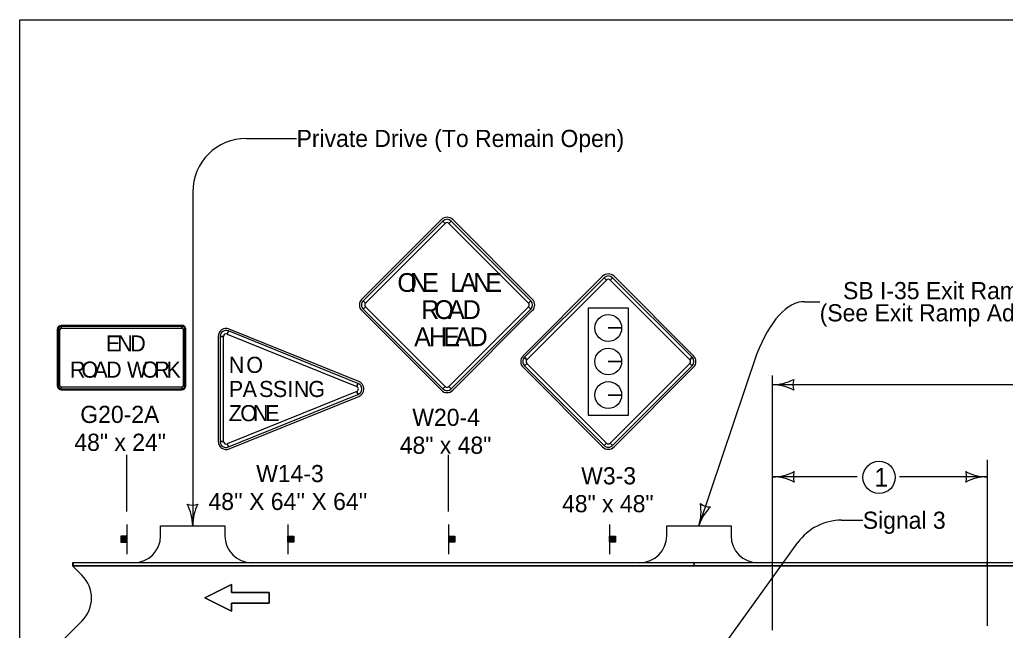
# Model space of a CAD drawing. Extents: x -2134934 to -2122394, y -2139046 to -2137036.
# Drawn here: x -2130232 to -2129313, y -2137605 to -2137036 of the extents above; entities that cross this region are included whole.
import ezdxf

# ---------------------------------------------------------------- set-up
doc = ezdxf.new("R2010")
doc.units = 0
for name, color, linetype in [('Barrier', 7, 'Continuous'), ('BridgeSuperStructureExisting', 7, 'Continuous'), ('Default', 7, 'Continuous'), ('DsnShtPlotIdentification', 7, 'Continuous'), ('DsnShtPlotShape', 7, 'Continuous')]:
    doc.layers.add(name, color=color, linetype=linetype)

msp = doc.modelspace()

# ---------------------------------------------------------------- linework, layer by layer
at = {"layer": 'Barrier'}
for p, q in [((-2129838.72, -2137222.31), (-2129912.96, -2137296.56)), ((-2129837.39, -2137223.64), (-2129835.18, -2137225.85)), ((-2129831.65, -2137225.85), (-2129829.44, -2137223.64)), ((-2129753.86, -2137296.56), (-2129828.11, -2137222.31)), ((-2129688.28, -2137275.12), (-2129762.53, -2137349.37)), ((-2129686.96, -2137276.45), (-2129684.75, -2137278.66)), ((-2129681.21, -2137278.66), (-2129679, -2137276.45)), ((-2129603.43, -2137349.37), (-2129677.68, -2137275.12)), ((-2129909.43, -2137300.09), (-2129911.64, -2137297.88)), ((-2129755.19, -2137297.88), (-2129757.4, -2137300.09)), ((-2129912.96, -2137307.16), (-2129838.72, -2137381.41)), ((-2129911.64, -2137305.84), (-2129909.43, -2137303.63)), ((-2129828.11, -2137381.41), (-2129753.86, -2137307.16)), ((-2129757.4, -2137303.63), (-2129755.19, -2137305.84)), ((-2130196.92, -2137324.64), (-2130196.92, -2137377.14)), ((-2130195.99, -2137324.64), (-2130194.42, -2137324.64)), ((-2130080.67, -2137320.89), (-2130193.17, -2137320.89)), ((-2130193.17, -2137323.39), (-2130193.17, -2137321.82)), ((-2130080.67, -2137321.82), (-2130080.67, -2137323.39)), ((-2130079.42, -2137324.64), (-2130077.86, -2137324.64)), ((-2130076.92, -2137377.14), (-2130076.92, -2137324.64)), ((-2130038.48, -2137329.01), (-2130037.31, -2137326.11)), ((-2129915.78, -2137373.25), (-2130036.61, -2137324.37)), ((-2129670.57, -2137323.34), (-2129683.07, -2137323.34)), ((-2129683.07, -2137323.34), (-2129670.57, -2137323.34)), ((-2130046.92, -2137331.32), (-2130046.92, -2137429.07)), ((-2130045.04, -2137331.32), (-2130041.92, -2137331.32)), ((-2129758.99, -2137352.9), (-2129761.2, -2137350.69)), ((-2129761.2, -2137358.65), (-2129758.99, -2137356.44)), ((-2129670.57, -2137354.59), (-2129683.07, -2137354.59)), ((-2129683.07, -2137354.59), (-2129670.57, -2137354.59)), ((-2129604.76, -2137350.69), (-2129606.96, -2137352.9)), ((-2129606.96, -2137356.44), (-2129604.76, -2137358.65)), ((-2129762.53, -2137359.98), (-2129688.28, -2137434.22)), ((-2129677.68, -2137434.22), (-2129603.43, -2137359.98)), ((-2129916.48, -2137374.98), (-2129917.66, -2137377.88)), ((-2130194.42, -2137377.14), (-2130195.99, -2137377.14)), ((-2130193.17, -2137379.95), (-2130193.17, -2137378.39)), ((-2130193.17, -2137380.89), (-2130080.67, -2137380.89)), ((-2130080.67, -2137378.39), (-2130080.67, -2137379.95)), ((-2130077.86, -2137377.14), (-2130079.42, -2137377.14)), ((-2129917.66, -2137382.52), (-2129916.48, -2137385.41)), ((-2129835.18, -2137377.87), (-2129837.39, -2137380.08)), ((-2129829.44, -2137380.08), (-2129831.65, -2137377.87)), ((-2130036.61, -2137436.03), (-2129915.78, -2137387.15)), ((-2129670.57, -2137385.84), (-2129683.07, -2137385.84)), ((-2129683.07, -2137385.84), (-2129670.57, -2137385.84)), ((-2130041.92, -2137429.07), (-2130045.04, -2137429.07)), ((-2129684.75, -2137430.69), (-2129686.96, -2137432.9)), ((-2129679, -2137432.9), (-2129681.21, -2137430.69)), ((-2130037.31, -2137434.29), (-2130038.48, -2137431.39))]:
    msp.add_line(p, q, dxfattribs=at)
for points in [[(-2129837.39, -2137223.64), (-2129911.64, -2137297.88), (-2129909.43, -2137300.09), (-2129835.18, -2137225.85), (-2129837.39, -2137223.64)], [(-2129755.19, -2137297.88), (-2129829.44, -2137223.64), (-2129831.65, -2137225.85), (-2129757.4, -2137300.09), (-2129755.19, -2137297.88)], [(-2129686.96, -2137276.45), (-2129761.2, -2137350.69), (-2129758.99, -2137352.9), (-2129684.75, -2137278.66), (-2129686.96, -2137276.45)], [(-2129604.76, -2137350.69), (-2129679, -2137276.45), (-2129681.21, -2137278.66), (-2129606.96, -2137352.9), (-2129604.76, -2137350.69)], [(-2129911.64, -2137305.84), (-2129837.39, -2137380.08), (-2129835.18, -2137377.87), (-2129909.43, -2137303.63), (-2129911.64, -2137305.84)], [(-2129829.44, -2137380.08), (-2129755.19, -2137305.84), (-2129757.4, -2137303.63), (-2129831.65, -2137377.87), (-2129829.44, -2137380.08)], [(-2129664.25, -2137304.73), (-2129701.71, -2137304.73), (-2129701.71, -2137404.62), (-2129664.25, -2137404.62), (-2129664.25, -2137304.73)], [(-2130195.99, -2137324.64), (-2130195.99, -2137377.14), (-2130194.42, -2137377.14), (-2130194.42, -2137324.64), (-2130195.99, -2137324.64)], [(-2130080.67, -2137321.82), (-2130193.17, -2137321.82), (-2130193.17, -2137323.39), (-2130080.67, -2137323.39), (-2130080.67, -2137321.82)], [(-2130077.86, -2137377.14), (-2130077.86, -2137324.64), (-2130079.42, -2137324.64), (-2130079.42, -2137377.14), (-2130077.86, -2137377.14)], [(-2129916.48, -2137374.98), (-2130037.31, -2137326.11), (-2130038.48, -2137329.01), (-2129917.66, -2137377.88), (-2129916.48, -2137374.98)], [(-2130045.04, -2137331.32), (-2130045.04, -2137429.07), (-2130041.92, -2137429.07), (-2130041.92, -2137331.32), (-2130045.04, -2137331.32)], [(-2129761.2, -2137358.65), (-2129686.96, -2137432.9), (-2129684.75, -2137430.69), (-2129758.99, -2137356.44), (-2129761.2, -2137358.65)], [(-2129679, -2137432.9), (-2129604.76, -2137358.65), (-2129606.96, -2137356.44), (-2129681.21, -2137430.69), (-2129679, -2137432.9)], [(-2130193.17, -2137379.95), (-2130080.67, -2137379.95), (-2130080.67, -2137378.39), (-2130193.17, -2137378.39), (-2130193.17, -2137379.95)], [(-2130037.31, -2137434.29), (-2129916.48, -2137385.41), (-2129917.66, -2137382.52), (-2130038.48, -2137431.39), (-2130037.31, -2137434.29)]]:
    msp.add_lwpolyline(points, close=True, dxfattribs=at)
for centre in [(-2129683.07, -2137323.34), (-2129683.07, -2137354.59), (-2129683.07, -2137385.84)]:
    msp.add_circle(centre, 12.5, dxfattribs=at)
for centre, radius, start, end in [((-2129833.41, -2137227.61), 7.5, 44.99999, 134.99974), ((-2129833.41, -2137227.61), 5.62, 44.99999, 134.99974), ((-2129833.41, -2137227.61), 2.5, 44.99999, 134.99974), ((-2129682.98, -2137280.43), 7.5, 44.99999, 134.99974), ((-2129682.98, -2137280.43), 5.62, 44.99999, 134.99974), ((-2129682.98, -2137280.43), 2.5, 44.99999, 134.99974), ((-2129907.66, -2137301.86), 7.5, 134.99974, 224.99995), ((-2129907.66, -2137301.86), 5.62, 134.99974, 224.99995), ((-2129907.66, -2137301.86), 2.5, 134.99974, 224.99995), ((-2129759.17, -2137301.86), 2.5, 315.00016, 44.9998), ((-2129759.17, -2137301.86), 5.62, 315.00016, 44.9998), ((-2129759.17, -2137301.86), 7.5, 315.00016, 44.9998), ((-2130193.17, -2137324.64), 3.75, 90.00021, 179.99985), ((-2130193.17, -2137324.64), 2.81, 90.00021, 179.99985), ((-2130193.17, -2137324.64), 1.25, 90.00021, 179.99985), ((-2130080.67, -2137324.64), 3.75, 0, 90.00021), ((-2130080.67, -2137324.64), 2.81, 0, 90.00021), ((-2130080.67, -2137324.64), 1.25, 0, 90.00021), ((-2130039.42, -2137331.32), 7.5, 67.97571, 179.99985), ((-2130039.42, -2137331.32), 5.62, 67.97571, 179.99985), ((-2130039.42, -2137331.32), 2.5, 67.97571, 179.99985), ((-2129757.23, -2137354.67), 7.5, 134.99974, 224.99995), ((-2129757.23, -2137354.67), 5.62, 134.99974, 224.99995), ((-2129757.23, -2137354.67), 2.5, 134.99974, 224.99995), ((-2129608.73, -2137354.67), 2.5, 315.00016, 44.9998), ((-2129608.73, -2137354.67), 5.62, 315.00016, 44.9998), ((-2129608.73, -2137354.67), 7.5, 315.00016, 44.9998), ((-2129918.59, -2137380.2), 5.62, 292.02456, 67.97541), ((-2129918.59, -2137380.2), 7.5, 292.02456, 67.97598), ((-2130193.17, -2137377.14), 3.75, 179.99985, 270.00006), ((-2130193.17, -2137377.14), 2.81, 179.99985, 270.00006), ((-2130193.17, -2137377.14), 1.25, 179.99985, 270.00006), ((-2130080.67, -2137377.14), 3.75, 270.00006, 0.00027), ((-2130080.67, -2137377.14), 2.81, 270.00006, 0.00027), ((-2130080.67, -2137377.14), 1.25, 270.00006, 0.00027), ((-2129918.59, -2137380.2), 2.5, 292.02456, 67.97541), ((-2129833.41, -2137376.11), 7.5, 224.99995, 315.00016), ((-2129833.41, -2137376.11), 5.62, 224.99995, 315.00016), ((-2129833.41, -2137376.11), 2.5, 224.99995, 315.00016), ((-2130039.42, -2137429.07), 7.5, 179.99985, 292.02456), ((-2130039.42, -2137429.07), 5.62, 179.99985, 292.02456), ((-2130039.42, -2137429.07), 2.5, 179.99985, 292.02456), ((-2129682.98, -2137428.92), 2.5, 224.99995, 315.00016), ((-2129682.98, -2137428.92), 7.5, 224.99995, 315.00016), ((-2129682.98, -2137428.92), 5.62, 224.99995, 315.00016)]:
    msp.add_arc(centre, radius, start, end, dxfattribs=at)
at = {"layer": 'BridgeSuperStructureExisting'}
for p, q in [((-2130020.59, -2137146.61), (-2129973.72, -2137146.61)), ((-2130070.59, -2137196.61), (-2130070.59, -2137507.67)), ((-2129500.02, -2137298.84), (-2129485.8, -2137298.84)), ((-2129544.75, -2137347.98), (-2129598.55, -2137507.67)), ((-2129530.12, -2137367.55), (-2129530.12, -2137605.16)), ((-2129305.21, -2137376.23), (-2129530.12, -2137376.23)), ((-2130131.95, -2137494.5), (-2130131.95, -2137441.62)), ((-2129831.95, -2137494.5), (-2129831.95, -2137441.62)), ((-2129329.62, -2137446.18), (-2129329.62, -2137601.07)), ((-2129450.84, -2137462.08), (-2129529.62, -2137462.08)), ((-2129329.62, -2137462.08), (-2129411.39, -2137462.08)), ((-2129465.57, -2137502.57), (-2129445.67, -2137502.57)), ((-2130131.95, -2137506.66), (-2130131.95, -2137534.16)), ((-2129981.95, -2137506.66), (-2129981.95, -2137534.16)), ((-2129831.95, -2137506.66), (-2129831.95, -2137534.16)), ((-2129681.95, -2137506.66), (-2129681.95, -2137534.16)), ((-2130137.28, -2137517.52), (-2130137.28, -2137523.11)), ((-2130136.96, -2137523.11), (-2130136.96, -2137517.52)), ((-2130136.73, -2137517.52), (-2130136.73, -2137523.11)), ((-2130136.41, -2137523.11), (-2130136.41, -2137517.52)), ((-2130136.19, -2137517.52), (-2130136.21, -2137523.11)), ((-2130135.78, -2137523.11), (-2130135.76, -2137517.52)), ((-2130135.55, -2137517.52), (-2130135.55, -2137523.11)), ((-2130135.12, -2137523.11), (-2130135.12, -2137517.52)), ((-2130134.75, -2137517.52), (-2130134.75, -2137523.11)), ((-2130134.43, -2137523.11), (-2130134.41, -2137517.52)), ((-2130134.2, -2137517.52), (-2130134.2, -2137523.11)), ((-2130133.94, -2137523.11), (-2130133.94, -2137517.52)), ((-2130133.6, -2137517.52), (-2130133.6, -2137523.11)), ((-2130133.4, -2137523.11), (-2130133.4, -2137517.52)), ((-2130133.17, -2137517.52), (-2130133.17, -2137523.11)), ((-2130132.91, -2137523.11), (-2130132.91, -2137517.52)), ((-2130132.65, -2137517.52), (-2130132.65, -2137523.11)), ((-2130132.36, -2137523.11), (-2130132.36, -2137517.52)), ((-2129981.54, -2137523.11), (-2129981.54, -2137517.52)), ((-2129981.26, -2137517.52), (-2129981.26, -2137523.11)), ((-2129980.99, -2137523.11), (-2129980.99, -2137517.52)), ((-2129980.73, -2137517.52), (-2129980.73, -2137523.11)), ((-2129980.51, -2137523.11), (-2129980.51, -2137517.52)), ((-2129980.3, -2137517.52), (-2129980.3, -2137523.11)), ((-2129979.96, -2137523.11), (-2129979.96, -2137517.52)), ((-2129979.7, -2137517.52), (-2129979.7, -2137523.11)), ((-2129979.47, -2137523.11), (-2129979.49, -2137517.52)), ((-2129979.16, -2137517.52), (-2129979.16, -2137523.11)), ((-2129978.78, -2137523.11), (-2129978.78, -2137517.52)), ((-2129978.35, -2137517.52), (-2129978.35, -2137523.11)), ((-2129978.12, -2137523.11), (-2129978.14, -2137517.52)), ((-2129977.71, -2137517.52), (-2129977.69, -2137523.11)), ((-2129977.49, -2137523.11), (-2129977.49, -2137517.52)), ((-2129977.17, -2137517.52), (-2129977.17, -2137523.11)), ((-2129976.94, -2137523.11), (-2129976.94, -2137517.52)), ((-2129976.62, -2137517.52), (-2129976.62, -2137523.11)), ((-2129831.54, -2137523.11), (-2129831.54, -2137517.52)), ((-2129831.26, -2137517.52), (-2129831.26, -2137523.11)), ((-2129830.99, -2137523.11), (-2129830.99, -2137517.52)), ((-2129830.73, -2137517.52), (-2129830.73, -2137523.11)), ((-2129830.51, -2137523.11), (-2129830.51, -2137517.52)), ((-2129830.3, -2137517.52), (-2129830.3, -2137523.11)), ((-2129829.96, -2137523.11), (-2129829.96, -2137517.52)), ((-2129829.7, -2137517.52), (-2129829.7, -2137523.11)), ((-2129829.47, -2137523.11), (-2129829.49, -2137517.52)), ((-2129829.16, -2137517.52), (-2129829.16, -2137523.11)), ((-2129828.78, -2137523.11), (-2129828.78, -2137517.52)), ((-2129828.35, -2137517.52), (-2129828.35, -2137523.11)), ((-2129828.12, -2137523.11), (-2129828.14, -2137517.52)), ((-2129827.71, -2137517.52), (-2129827.69, -2137523.11)), ((-2129827.49, -2137523.11), (-2129827.49, -2137517.52)), ((-2129827.17, -2137517.52), (-2129827.17, -2137523.11)), ((-2129826.94, -2137523.11), (-2129826.94, -2137517.52)), ((-2129826.62, -2137517.52), (-2129826.62, -2137523.11)), ((-2129681.54, -2137523.11), (-2129681.54, -2137517.52)), ((-2129681.26, -2137517.52), (-2129681.26, -2137523.11)), ((-2129680.99, -2137523.11), (-2129680.99, -2137517.52)), ((-2129680.73, -2137517.52), (-2129680.73, -2137523.11)), ((-2129680.51, -2137523.11), (-2129680.51, -2137517.52)), ((-2129680.3, -2137517.52), (-2129680.3, -2137523.11)), ((-2129679.96, -2137523.11), (-2129679.96, -2137517.52)), ((-2129679.7, -2137517.52), (-2129679.7, -2137523.11)), ((-2129679.48, -2137523.11), (-2129679.49, -2137517.52)), ((-2129679.16, -2137517.52), (-2129679.16, -2137523.11)), ((-2129678.78, -2137523.11), (-2129678.78, -2137517.52)), ((-2129678.35, -2137517.52), (-2129678.35, -2137523.11)), ((-2129678.13, -2137523.11), (-2129678.14, -2137517.52)), ((-2129677.71, -2137517.52), (-2129677.69, -2137523.11)), ((-2129677.49, -2137523.11), (-2129677.49, -2137517.52)), ((-2129677.17, -2137517.52), (-2129677.17, -2137523.11)), ((-2129676.94, -2137523.11), (-2129676.94, -2137517.52)), ((-2129676.63, -2137517.52), (-2129676.63, -2137523.11)), ((-2129647.56, -2137718.98), (-2129506.09, -2137523.28)), ((-2130182.57, -2137545.16), (-2130173.79, -2137553.95)), ((-2128680.12, -2137545.16), (-2130182.57, -2137545.16)), ((-2130182.57, -2137545.16), (-2130173.78, -2137553.95)), ((-2130015.59, -2137542.16), (-2130125.59, -2137542.16)), ((-2129543.56, -2137542.16), (-2129653.56, -2137542.16)), ((-2130173.78, -2137596.37), (-2130191.36, -2137613.95)), ((-2130173.79, -2137596.38), (-2130191.36, -2137613.95))]:
    msp.add_line(p, q, dxfattribs=at)
for points in [[(-2130100.59, -2137517.16), (-2130100.59, -2137507.67), (-2130040.59, -2137507.67), (-2130040.59, -2137517.16)], [(-2129628.56, -2137517.16), (-2129628.56, -2137507.67), (-2129568.56, -2137507.67), (-2129568.56, -2137517.16)], [(-2130034.3, -2137579.99), (-2130034.3, -2137587.49), (-2130059.3, -2137574.99), (-2130034.3, -2137562.49), (-2130034.3, -2137569.99), (-2129999.3, -2137569.99), (-2129999.3, -2137579.99), (-2130034.3, -2137579.99)]]:
    msp.add_lwpolyline(points, dxfattribs=at)
for points in [[(-2130132.05, -2137523.11), (-2130132.05, -2137517.48), (-2130137.67, -2137517.48), (-2130137.67, -2137523.11)], [(-2129981.86, -2137523.11), (-2129981.86, -2137517.48), (-2129976.23, -2137517.48), (-2129976.23, -2137523.11)], [(-2129831.86, -2137523.11), (-2129831.86, -2137517.48), (-2129826.23, -2137517.48), (-2129826.23, -2137523.11)], [(-2129681.86, -2137523.11), (-2129681.86, -2137517.48), (-2129676.23, -2137517.48), (-2129676.23, -2137523.11)], [(-2129999.3, -2137579.99), (-2129999.3, -2137569.99), (-2130034.3, -2137569.99), (-2130034.3, -2137562.49), (-2130059.3, -2137574.99), (-2130034.3, -2137587.49), (-2130034.3, -2137579.99)]]:
    msp.add_lwpolyline(points, close=True, dxfattribs=at)
msp.add_circle((-2129430.48, -2137462.58), 15, dxfattribs=at)
for centre, radius, start, end in [((-2130020.59, -2137196.61), 50, 90, 180), ((-2129529.62, -2137419.58), 42.5, 270, 298.07249), ((-2129493.99, -2137462.08), 16.42, 162.26665, 197.73335), ((-2129365.26, -2137462.08), 16.42, 342.26665, 17.73335), ((-2129329.62, -2137419.58), 42.5, 241.92751, 270), ((-2129529.62, -2137504.58), 42.5, 61.92751, 90), ((-2129329.62, -2137504.58), 42.5, 90, 118.07249), ((-2129465.57, -2137552.57), 50, 90, 144.13795), ((-2130125.59, -2137517.16), 25, 270, 360), ((-2130015.59, -2137517.16), 25, 180, 270), ((-2129653.56, -2137517.16), 25, 270, 360), ((-2129543.56, -2137517.16), 25, 180, 270), ((-2130195, -2137575.16), 30, 315, 45), ((-2130195, -2137575.16), 30, 315, 45)]:
    msp.add_arc(centre, radius, start, end, dxfattribs=at)
msp.add_ellipse((-2129500.02, -2137511.77), major_axis=(0, 212.93), ratio=0.328743, start_param=0, end_param=0.693162, dxfattribs=at)
at = {"layer": 'Default'}
msp.add_lwpolyline([(-2130231.95, -2137035.95), (-2127096.96, -2137035.95), (-2127096.96, -2139045.94), (-2130231.95, -2139045.94)], close=True, dxfattribs=at)
at = {"layer": 'DsnShtPlotIdentification'}
for p, q in [((-2128680.12, -2137542.16), (-2130182.57, -2137542.16)), ((-2130182.57, -2137542.16), (-2130182.57, -2137545.16)), ((-2129602.5, -2137542.16), (-2130182.57, -2137542.16)), ((-2128680.12, -2137545.16), (-2130182.57, -2137545.16)), ((-2130182.57, -2137545.16), (-2129603.51, -2137545.16)), ((-2130181.95, -2137542.16), (-2130181.95, -2137545.16)), ((-2129602.5, -2137542.16), (-2129603.51, -2137545.16)), ((-2129603.51, -2137545.16), (-2129602.5, -2137542.16)), ((-2129603.51, -2137545.16), (-2129329.62, -2137545.16)), ((-2129329.62, -2137542.16), (-2129602.5, -2137542.16)), ((-2129329.62, -2137542.16), (-2129329.62, -2137545.16)), ((-2129296.37, -2137542.16), (-2129329.62, -2137542.16)), ((-2129329.62, -2137545.16), (-2129329.62, -2137542.16)), ((-2129329.62, -2137545.16), (-2129296.24, -2137545.16))]:
    msp.add_line(p, q, dxfattribs=at)
msp.add_lwpolyline([(-2130182.37, -2137545.16), (-2128872.37, -2137545.16)], dxfattribs=at)
at = {"layer": 'DsnShtPlotShape'}
for centre, radius, start, end in [((-2129530.12, -2137333.73), 42.5, 270, 298.07249), ((-2129494.48, -2137376.23), 16.42, 162.26665, 197.73335), ((-2129530.12, -2137418.73), 42.5, 61.92751, 90), ((-2130071.03, -2137472.04), 16.42, 252.97281, 288.43951), ((-2130113.08, -2137508.19), 42.5, 0.70616, 28.77865), ((-2130028.09, -2137507.15), 42.5, 152.63367, 180.70616), ((-2129638.99, -2137494.6), 42.5, 342.08492, 10.15741), ((-2129558.12, -2137520.74), 42.5, 134.01243, 162.08492), ((-2129587.59, -2137473.76), 16.42, 234.35157, 269.81827)]:
    msp.add_arc(centre, radius, start, end, dxfattribs=at)

# ---------------------------------------------------------------- texts
at = {"layer": 'Barrier'}
for s, height, p in [('O', 17.5, (-2129879.7, -2137289.67)), ('N', 17.5, (-2129867.92, -2137289.67)), ('E', 17.5, (-2129856.7, -2137289.67)), ('L', 17.5, (-2129830.45, -2137289.67)), ('A', 17.5, (-2129821.25, -2137289.67)), ('N', 17.5, (-2129808.98, -2137289.67)), ('E', 17.5, (-2129797.75, -2137289.67)), ('R', 17.5, (-2129857.59, -2137314.98)), ('O', 17.5, (-2129845.3, -2137314.98)), ('A', 17.5, (-2129832.46, -2137314.98)), ('D', 17.5, (-2129818.81, -2137314.98)), ('A', 17.5, (-2129864.03, -2137340.3)), ('H', 17.5, (-2129850.16, -2137340.3)), ('E', 17.5, (-2129836.95, -2137340.3)), ('A', 17.5, (-2129826.23, -2137340.3)), ('D', 17.5, (-2129812.37, -2137340.3)), ('E', 15, (-2130151.6, -2137345.26)), ('N', 15, (-2130140.98, -2137345.26)), ('D', 15, (-2130128.89, -2137345.26)), ('R', 15, (-2130185.06, -2137369.64)), ('O', 15, (-2130174.38, -2137369.64)), ('A', 15, (-2130163.22, -2137369.64)), ('D', 15, (-2130151.36, -2137369.64)), ('W', 15, (-2130131.91, -2137369.64)), ('O', 15, (-2130118.18, -2137369.64)), ('R', 15, (-2130106.41, -2137369.64)), ('K', 15, (-2130095.11, -2137369.64)), ('N', 15, (-2130036.95, -2137365.2)), ('O', 15, (-2130020.61, -2137365.2)), ('P', 15, (-2130036.95, -2137387.7)), ('A', 15, (-2130024.06, -2137387.7)), ('S', 15, (-2130008.71, -2137387.7)), ('S', 15, (-2129995.82, -2137387.7)), ('I', 15, (-2129982.22, -2137387.7)), ('N', 15, (-2129976.36, -2137387.7)), ('G', 15, (-2129962.77, -2137387.7)), ('G20-2A', 16, (-2130175.45, -2137411.89)), ('Z', 15, (-2130036.95, -2137410.2)), ('O', 15, (-2130026.21, -2137410.2)), ('N', 15, (-2130014.38, -2137410.2)), ('E', 15, (-2130003.02, -2137410.2)), ('W20-4', 16, (-2129865.78, -2137414.61)), ('48" x 24"', 16, (-2130180.99, -2137437.89)), ('48" x 48"', 16, (-2129877.48, -2137440.61)), ('W14-3', 16, (-2130011.41, -2137467.03)), ('W3-3', 16, (-2129708.27, -2137469.14)), ("48'' X 64'' X 64''", 16, (-2130055.9, -2137493.03)), ('48" x 48"', 16, (-2129726.15, -2137495.14))]:
    msp.add_text(s, height=height, dxfattribs=at).set_placement(p)
at = {"layer": 'BridgeSuperStructureExisting'}
for s, height, p in [('Private Drive (To Remain Open)', 16, (-2129973.72, -2137154.61)), ('SB I-35 Exit Ramp (To Remain Open)', 16, (-2129464.08, -2137296.49)), ('(See Exit Ramp Advanced Signing on J.5)', 16, (-2129485.85, -2137317.19)), ('1', 17.5, (-2129434.94, -2137471.33)), ('Signal 3', 16, (-2129445.67, -2137510.57))]:
    msp.add_text(s, height=height, dxfattribs=at).set_placement(p)

doc.saveas('drawing.dxf')
